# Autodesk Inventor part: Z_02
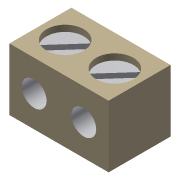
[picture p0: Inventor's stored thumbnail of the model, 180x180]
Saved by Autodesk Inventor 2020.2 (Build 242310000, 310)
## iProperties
GlobalPropertyList: <PropertyList/>
Manager: www.cadconsulting.pl
Company: Fabian Stasiak CAD Consulting
Created: 2014-09
Part Number: Z_02
Material: Ogólny
Document SubType Name: Modeling
Designer: F.Stasiak
Density: 1 g/cm^3
Appearance: Beżowa
Categories: <MemberInstance><Categories><Category DisplayName="" Mnemonic="CABLEANDHARNESS" InternalName="e4a7e005-5e42-4d16-b293-125e7f0d0512"><Category DisplayName="" Mne
Catalog Web Link: www.expertbooks.pl
Author: F.Stasiak
Subject: Zbiór ćwiczeń. Autodesk Inventor 2020. Kurs Professional
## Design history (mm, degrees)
sketch "Szkic1"
  geometry: L1 (-4, 2.5)-(4, 2.5); L2 (4, 2.5)-(4, -2.5); L3 (4, -2.5)-(-4, -2.5); L4 (-4, -2.5)-(-4, 2.5); L5 (-4, 2.5)-(4, -2.5); L6 (4, 2.5)-(-4, -2.5); 1 further point
  constraints: 12 end point, 2 midpoint, 2 parallel, 1 horizontal, 1 perpendicular
  dimensions: "d0" = 8 distance of L2.end L3.end; "d1" = 5 distance of L1.end L2.end
extrude "Wyciągnięcie proste1" new body sketch "Szkic1" distance "d2" = 5; taper "d3" = 0 deg
sketch "Szkic2"
  geometry: L1 (8, 0)-(0, 0) reference; L2 (8, 0)-(8, 5) reference; L3 (2, 2.5)-(6, 2.5); C1 r 1 at (2, 2.5); C2 r 1 at (6, 2.5); 3 further points
  constraints: 3 midpoint, 2 centre point, 2 end point, 1 horizontal, 1 horizontal alignment, 1 vertical alignment
  dimensions: "d5" = 2 diameter of C1; "d6" = 2 diameter of C2; "d7" = 4 distance of L3.start L3.end
extrude "Wyciągnięcie proste2" cut sketch "Szkic2" distance "d8" = 4; taper "d9" = 0 deg
sketch "Szkic3"
  geometry: L1 (-2, 0)-(2, 0); C1 r 1.5 at (-2, 0); C2 r 1.5 at (2, 0); 2 further points
  constraints: 2 centre point, 2 end point, 1 coincident, 1 horizontal, 1 midpoint
  dimensions: "d10" = 3 diameter of C1; "d11" = 3 diameter of C2; "d12" = 4 distance of L1.start L1.end
extrude "Wyciągnięcie proste3" cut sketch "Szkic3" distance "d13" = 0.5; taper "d14" = 0 deg
sketch "Szkic4"
  geometry: L1 (-1, -1.118)-(1, 1.118); L2 (1, -2.5)-(1, 1.5) reference; L3 (-1.188, -0.916)-(0.778, 1.282); L4 (-0.778, -1.282)-(1.188, 0.916); L5 (3, -1.118)-(5, 1.118); L6 (-0.205, 0.183)-(0.205, -0.183); L7 (3.795, 0.183)-(4.205, -0.183); L8 (2.812, -0.916)-(4.778, 1.282); L9 (3.222, -1.282)-(5.188, 0.916); A1 r 1.5 centre (0, 0) between (-1, -1.118) and (1, 1.118) reference; A2 r 1.5 centre (4, 0) between (3, -1.118) and (5, 1.118) reference; A3 r 1.5 centre (4, 0) between (3, -1.118) and (5, 1.118) reference; 3 further points
  constraints: 18 point on circle, 16 end point, 8 midpoint, 5 parallel, 2 coincident, 1 point on line
  dimensions: "d15" = 0.55 distance between parallel lines of L3 L4
extrude "Wyciągnięcie proste4" cut sketch "Szkic4" distance "d17" = 0.5; taper "d18" = 0 deg
node "Bryła1"
node "Pętla rzutowana1"
node "Pętla rzutowana2"
